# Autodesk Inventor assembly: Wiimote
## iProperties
Created: 2010-07
Part Number: Wiimote
Document SubType Name: Assembly
Designer: eric
Norme de conversion: STEP AP214IS
Nom du fichier: C:\Users\eric\Documents\Inventor\CIT2008\Maquettes solidworks\Wiimote M.Bouquin\Assemblage1.stp
Préprocesseur: Autodesk Inventor 2010
Postprocesseur: Build: 342, Release: 2008 SP3 - Date: Tue 05/27/2008
Unités envoyées: MILLIMETERS
Incertitude: 0.01
Author: eric
